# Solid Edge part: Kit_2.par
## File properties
Author: bmolnar
Last saved by: bmolnar
Revision: 77
Sűrűség: 0,000 kg/m^3
Pontosság: 0,990
Username: bmolnar
Dokumentum tartalom típus: 0
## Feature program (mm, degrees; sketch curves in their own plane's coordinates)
base feature "unnamed BaseFeature 1"
sketch for "unnamed Hole 1" plane through (17.575, 12.675, 89.2) normal (0, 0, 1) x-axis (0.38075, -0.924678, 0)
  hole centre (-3.8102, 0.136) bore radius 2.4585
hole "unnamed Hole 1" through
sketch for "unnamed Hole 2" plane through (17.575, 12.675, 89.2) normal (0, 0, 1) x-axis (0.38075, -0.924678, 0)
  hole centre (26.2418, -12.2384) bore radius 2.4585
hole "unnamed Hole 2" through
sketch for "unnamed Hole 3" plane through (17.575, 12.675, 89.2) normal (0, 0, 1) x-axis (0.38075, -0.924678, 0)
  hole centre (-16.1846, -29.9161) bore radius 2.4585
hole "unnamed Hole 3" through
sketch for "unnamed Hole 4" plane through (17.575, 12.675, 89.2) normal (0, 0, 1) x-axis (0.38075, -0.924678, 0)
  hole centre (13.8675, -42.2904) bore radius 2.4585
hole "unnamed Hole 4" through
pattern "unnamed Pattern 1" of "unnamed Hole 1", "unnamed Hole 2", "unnamed Hole 3", "unnamed Hole 4"
thread "unnamed Thread 1"
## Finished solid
Body 1: solid body, 318 faces, 747 edges, 450 vertices, 4 internal voids.
  Faces by surface: plane 145, cylinder 71, swept 55, torus 25, cone 21, spline 1
  Edges by curve: line 433, circle 187, spline 122, curve on surface 4, intersection 1
Bounding box of the edges (mm; curved faces can reach further): 49.000 x 49.000 x 14.100, from (-24.5, -24.5, 79.6) to (24.5, 24.5, 93.7).
Cylindrical faces by radius (mm): R0.2 x30, R0.335 x1, R0.5307 x1, R1.25 x1, R2.4585 x4, R2.5402 x12, R2.6 x4, R3.75 x4, R4 x4, R4.283 x1, R4.5 x4, R6.27 x1, R6.85 x1, R7 x1, R8.16 x1, R8.25 x1
Conical faces (half-angle, radius in mm at the cone's reference point): 0.5 deg R8 x4, 0.5 deg R8.6 x1, 0.5 deg R10.6 x1, 3 deg R8.205 x1, 7 deg R7.5925 x1, 14 deg R6.135 x1, 14 deg R6.4811 x1, 17 deg R6.135 x1, 23 deg R6.829 x1, 42.5 deg R6.1233 x1, 45 deg R2.8085 x4, 45 deg R7 x1, 84 deg R6.4608 x1, 85 deg R7.9463 x1, 87 deg R6.1765 x1
Toroidal faces (ring radius, tube radius in mm): R2.9402 r0.4 x12, R3.55 r0.2 x8, R6.8057 r0.2025 x1, R7.2522 r0.2925 x1, R7.96 r0.2 x1, R9.0957 r0.5 x1, R10.1043 r0.5 x1
Planar faces by outward normal: +x 11, +y 12, +z 21, -x 9, -y 12, -z 3, oblique 77
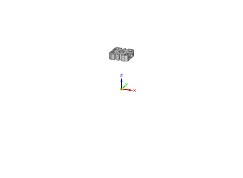
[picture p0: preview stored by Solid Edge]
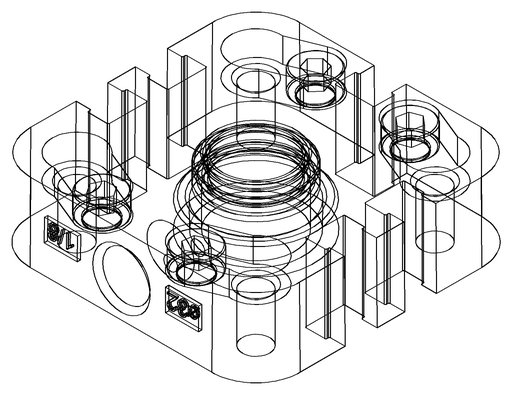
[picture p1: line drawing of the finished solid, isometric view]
